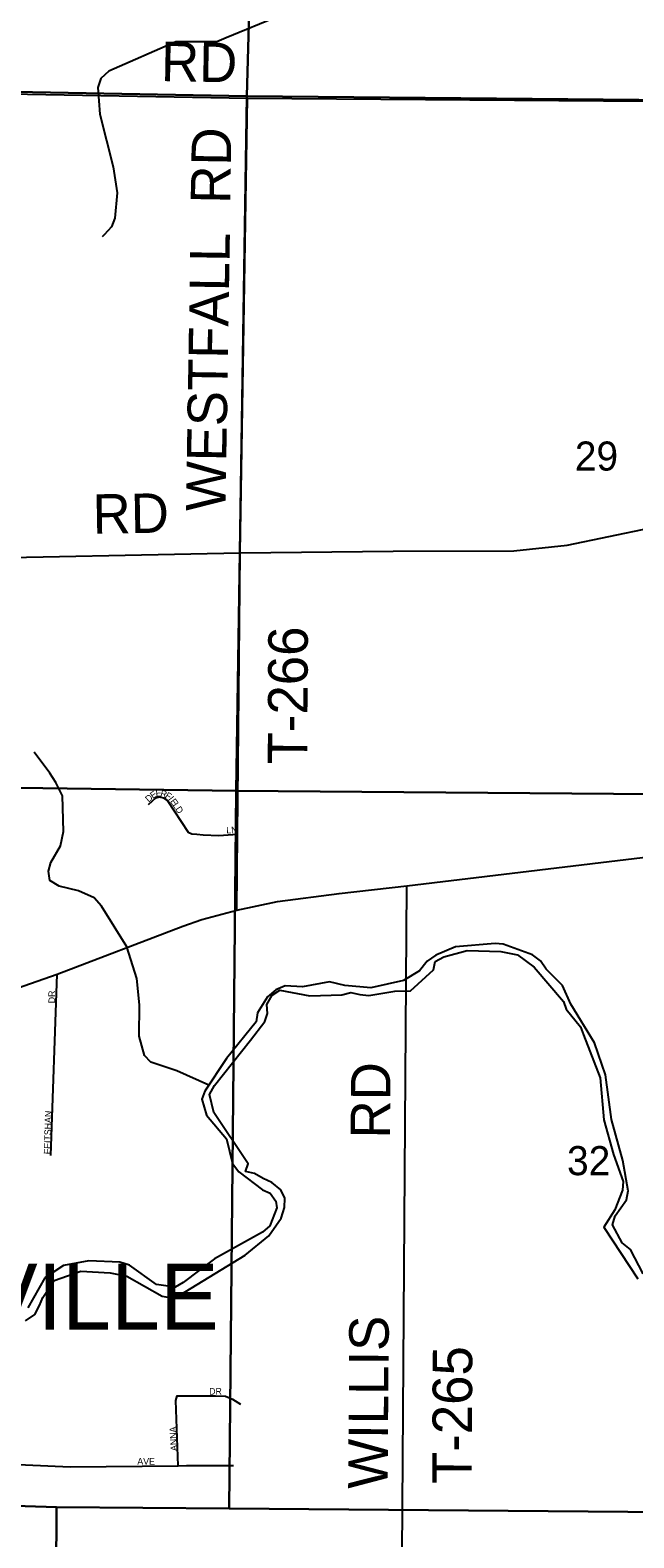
# Model space of a CAD drawing. Extents: x 0 to 1391, y -24 to 440.
# Drawn here: x 133.89 to 151.26, y 345.88 to 389.28 of the extents above; entities that cross this region are included whole.
import ezdxf

# ---------------------------------------------------------------- set-up
doc = ezdxf.new("R2010")
doc.units = 0
for name, color, linetype in [('GM_X_Corporation_Text', 7, 'Continuous'), ('GM_X_County_Road', 7, 'Continuous'), ('GM_X_County_Road_Text', 7, 'Continuous'), ('GM_X_Major_River', 7, 'Continuous'), ('GM_X_Minor_River', 7, 'Continuous'), ('GM_X_Section', 7, 'Continuous'), ('GM_X_Section_Text', 7, 'Continuous'), ('GM_X_Township_Road', 7, 'Continuous'), ('GM_X_Township_Road_Text', 7, 'Continuous'), ('GM_X_Township_Subdivision', 7, 'Continuous'), ('GM_X_Township_Subdivision_Text', 7, 'Continuous'), ('GM_X_US_Route', 7, 'Continuous')]:
    doc.layers.add(name, color=color, linetype=linetype)

msp = doc.modelspace()

# ---------------------------------------------------------------- linework, layer by layer
at = {"layer": 'GM_X_County_Road'}
msp.add_lwpolyline([(119.996, 374.457), (122.901, 374.439), (125.771, 374.251), (131.419, 374.061), (139.93, 374.235), (144.334, 374.282), (147.812, 374.287), (149.343, 374.454), (155.345, 375.705), (156.996, 376.105), (158.957, 376.654), (160.487, 377.208)], dxfattribs=at)
at = {"layer": 'GM_X_Major_River'}
for points in [[(151.531, 353.477), (151.172, 354.183), (150.931, 354.37), (150.652, 354.885), (150.725, 355.149), (151.053, 355.606), (151.096, 355.864), (150.945, 356.741), (150.617, 357.917), (150.451, 359.204), (150.133, 360.13), (149.453, 361.237), (149.212, 361.782), (148.741, 362.247), (148.578, 362.493), (148.346, 362.657), (147.499, 362.97), (147.271, 362.989), (146.127, 362.89), (145.567, 362.65), (145.32, 362.48), (145.094, 362.196), (144.632, 361.924), (143.691, 361.714)], [(140.643, 360.739), (140.724, 360.973), (140.706, 361.232), (140.855, 361.502), (141.079, 361.642), (141.936, 361.482), (142.858, 361.51), (143.118, 361.573), (143.383, 361.522), (143.634, 361.487), (144.382, 361.617), (144.839, 361.623), (145.498, 362.226), (145.548, 362.468), (145.794, 362.6), (146.467, 362.785), (147.434, 362.758), (147.912, 362.658), (148.392, 362.307), (149.242, 361.317), (149.314, 361.096), (149.73, 360.586), (149.818, 360.357), (150.297, 359.124), (150.396, 357.914), (150.682, 356.913), (150.957, 356.133), (150.937, 355.89), (150.713, 355.324), (150.399, 354.821), (151.376, 353.336)], [(143.691, 361.714), (142.946, 361.774), (142.507, 361.881), (141.728, 361.736), (141.226, 361.769), (140.965, 361.652), (140.717, 361.452), (140.435, 360.994), (140.399, 360.736), (139.542, 359.674), (138.915, 358.736), (138.835, 358.509), (138.963, 358.043), (139.537, 357.364), (139.714, 356.654), (139.9, 356.415), (140.576, 355.9), (140.795, 355.805), (140.958, 355.574), (140.992, 355.376), (140.792, 354.863), (140.575, 354.677), (139.198, 353.906), (138.295, 353.231), (138.064, 353.091), (137.525, 353.17), (136.751, 353.732), (136.471, 353.813), (135.581, 353.853), (134.847, 353.714), (134.308, 353.36), (133.82, 352.503)], [(133.759, 352.124), (134.022, 352.309), (134.164, 352.565), (134.259, 352.799), (134.581, 353.286), (135.347, 353.553), (136.191, 353.507), (136.677, 353.414), (137.694, 352.84), (137.899, 352.798), (138.174, 352.854), (140.076, 354.018), (140.764, 354.575), (141.116, 355.077), (141.213, 355.387), (141.218, 355.653), (141.108, 355.898), (140.846, 356.108), (140.597, 356.219), (140.348, 356.368), (140.083, 356.426), (140.163, 356.645), (139.178, 358.123), (139.051, 358.642), (139.193, 358.898), (140.23, 360.207), (140.643, 360.739)]]:
    msp.add_lwpolyline(points, dxfattribs=at)
at = {"layer": 'GM_X_Minor_River'}
for points in [[(144.297, 392.08), (144.108, 391.81), (143.667, 391.447), (143.272, 390.262), (143.034, 390.16), (142.332, 390.067), (141.076, 389.696), (139.534, 389.057), (139.266, 388.948), (138.085, 388.94), (136.151, 388.095), (135.926, 387.887), (135.838, 387.63), (135.892, 386.862), (136.283, 385.343), (136.39, 384.597), (136.324, 383.869), (136.228, 383.62), (136.025, 383.388), (135.963, 383.329)], [(139.029, 358.906), (138.113, 359.321), (137.367, 359.569), (137.184, 359.766), (137.028, 360.32), (137.037, 361.218), (136.965, 361.982), (136.677, 362.891), (135.941, 364.059), (135.728, 364.303), (135.286, 364.501), (134.727, 364.635), (134.459, 364.805), (134.422, 365.065), (134.484, 365.321), (134.76, 365.799), (134.851, 366.207), (134.818, 367.236), (134.626, 367.623), (134.46, 367.888), (134.004, 368.494)]]:
    msp.add_lwpolyline(points, dxfattribs=at)
at = {"layer": 'GM_X_Section'}
for points in [[(140.682, 407.534), (140.129, 387.379), (120.081, 387.754), (120.596, 407.894)], [(140.682, 407.534), (160.868, 407.573), (160.643, 387.189), (140.129, 387.379)], [(120.081, 387.754), (140.129, 387.379), (139.822, 367.382), (119.659, 367.662)], [(140.129, 387.379), (160.643, 387.189), (160.337, 367.223), (139.822, 367.382)], [(119.659, 367.662), (139.822, 367.382), (139.614, 346.725), (134.652, 346.763), (119.229, 347.252)], [(139.822, 367.382), (160.337, 367.223), (160.197, 346.564), (154.538, 346.603), (139.614, 346.725)], [(119.229, 347.252), (134.652, 346.763), (134.552, 327.163), (118.78, 327.297), (118.783, 327.433)], [(134.652, 346.763), (139.614, 346.725), (154.538, 346.603), (154.461, 326.988), (134.552, 327.163)]]:
    msp.add_lwpolyline(points, close=True, dxfattribs=at)
at = {"layer": 'GM_X_Township_Road'}
for points in [[(120.086, 387.691), (140.147, 387.318), (160.623, 387.168)], [(139.835, 363.949), (139.855, 366.136), (139.93, 374.235), (140.147, 387.318)], [(144.58, 342.653), (144.735, 364.651)]]:
    msp.add_lwpolyline(points, dxfattribs=at)
at = {"layer": 'GM_X_Township_Subdivision'}
for points in [[(137.295, 366.989), (137.503, 367.185), (137.606, 367.207), (137.728, 367.185), (137.834, 367.118), (138.44, 366.197), (138.543, 366.146), (138.684, 366.136), (138.873, 366.117), (139.316, 366.101), (139.855, 366.136)], [(134.488, 356.888), (134.665, 362.108)], [(138.153, 347.95), (138.082, 349.83), (138.117, 349.966), (139.223, 349.964), (139.512, 349.956), (139.716, 349.866), (139.941, 349.731)], [(130.766, 347.996), (133.757, 347.976), (135.037, 347.924), (138.153, 347.95), (138.389, 347.963), (139.74, 347.957)]]:
    msp.add_lwpolyline(points, dxfattribs=at)
at = {"layer": 'GM_X_US_Route'}
for points in [[(144.735, 364.651), (155.337, 365.926), (160.287, 366.576), (162.429, 366.863), (164.252, 367.094), (165.088, 367.2), (165.666, 367.329), (168.443, 368.339), (171.195, 369.322), (173.499, 370.166), (174.335, 370.455), (174.852, 370.599), (175.978, 370.865), (178, 371.259)], [(139.835, 363.949), (141.008, 364.199), (142.786, 364.431), (144.735, 364.651)], [(129.608, 360.402), (129.693, 360.428), (130.946, 360.852), (132.767, 361.444), (134.665, 362.108), (138.284, 363.484), (138.831, 363.68), (139.835, 363.949)]]:
    msp.add_lwpolyline(points, dxfattribs=at)

# ---------------------------------------------------------------- texts
at = {"layer": 'GM_X_Corporation_Text'}
msp.add_text('GREENVILLE', height=1.8939, rotation=0, dxfattribs=at).set_placement((123.41, 351.875))
at = {"layer": 'GM_X_County_Road_Text'}
msp.add_text('RD', height=1.1364, rotation=0.9891, dxfattribs=at).set_placement((135.697, 374.78))
at = {"layer": 'GM_X_Section_Text'}
for s, p in [('29', (149.566, 376.601)), ('32', (149.341, 356.318))]:
    msp.add_text(s, height=0.8371, rotation=0, dxfattribs=at).set_placement(p)
at = {"layer": 'GM_X_Township_Road_Text'}
for s, rotation, p in [('RD', 359.0128, (137.649, 387.814)), ('RD', 89.0118, (139.645, 384.275)), ('WESTFALL', 89.0781, (139.511, 375.424)), ('T-266', 89.7193, (141.864, 368.14)), ('RD', 89.5063, (144.245, 357.371)), ('WILLIS', 89.5939, (144.178, 347.287)), ('T-265', 89.7193, (146.597, 347.424))]:
    msp.add_text(s, height=1.1364, rotation=rotation, dxfattribs=at).set_placement(p)
at = {"layer": 'GM_X_Township_Subdivision_Text'}
for s, height, rotation, p in [('D', 0.189, 40.8384, (137.3, 367.042)), ('E', 0.189, 33.5461, (137.421, 367.147)), ('E', 0.189, 5.61, (137.51, 367.213)), ('R', 0.189, 345.843, (137.625, 367.227)), ('F', 0.189, 328.8113, (137.757, 367.196)), ('I', 0.189, 307.9018, (137.857, 367.139)), ('E', 0.189, 305.0994, (137.907, 367.075)), ('L', 0.189, 303.6939, (137.983, 366.967)), ('D', 0.189, 303.7027, (138.057, 366.856)), ('LN', 0.1894, 3.0113, (139.54, 366.152)), ('DR', 0.1894, 90, (134.606, 361.267)), ('FEITSHAN', 0.1894, 88.2912, (134.472, 356.918)), ('DR', 0.1894, 0, (139.041, 350.002)), ('ANNA', 0.1894, 92.8638, (138.123, 348.382)), ('AVE', 0.1894, 0, (136.975, 347.986))]:
    msp.add_text(s, height=height, rotation=rotation, dxfattribs=at).set_placement(p)

doc.saveas('drawing.dxf')
